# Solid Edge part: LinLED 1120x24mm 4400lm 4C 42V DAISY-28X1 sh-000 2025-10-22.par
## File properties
Author: patryk.ciesielski
Template: iso metric part.par
Last saved by: patryk.ciesielski
Revision: 4
Application: Solid Edge
Gęstość: 0.000 kg/m^3
Dokładność: 0.990
Username: patryk.ciesielski
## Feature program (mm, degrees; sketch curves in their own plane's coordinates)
body "unnamed Body 1"
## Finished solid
Body 1: solid body, 3530 faces, 10488 edges, 7290 vertices.
  Faces by surface: plane 2790, cylinder 682, swept 28, sphere 18, cone 4, spline 4, torus 4
  Edges by curve: line 8552, circle 1646, ellipse 154, curve on surface 136
Bounding box of the edges (mm; curved faces can reach further): 1119.000 x 24.000 x 4.330, from (-559.5, -12, 0) to (559.5, 12, 4.33).
Cylindrical faces by radius (mm): R0.0495 x4, R0.0647 x8, R0.0649 x8, R0.1 x20, R0.1164 x4, R0.1314 x16, R0.1729 x4, R0.2 x448, R0.2289 x4, R0.47 x8, R0.5 x56, R0.6 x4, R0.625 x4, R0.75 x8, R1 x4, R1.0277 x4, R1.05 x43, R1.8 x35
Conical faces (half-angle, radius in mm at the cone's reference point): 36.872 deg R0.8536 x4
Toroidal faces (ring radius, tube radius in mm): R1.2 r0.1 x4
Spherical faces by radius (mm): R0.1 x10, R0.5 x8
Planar faces by outward normal: +x 281, +y 307, +z 589, -x 281, -y 307, -z 13, oblique 1012
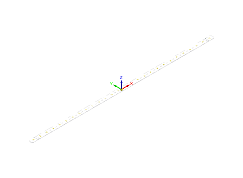
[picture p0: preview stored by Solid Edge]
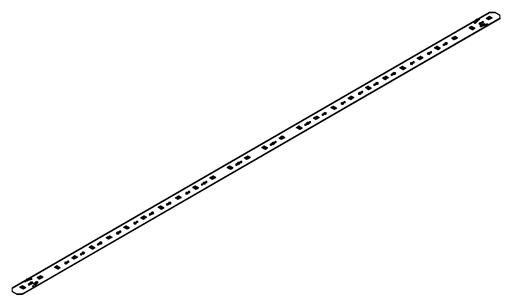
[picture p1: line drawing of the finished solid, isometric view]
